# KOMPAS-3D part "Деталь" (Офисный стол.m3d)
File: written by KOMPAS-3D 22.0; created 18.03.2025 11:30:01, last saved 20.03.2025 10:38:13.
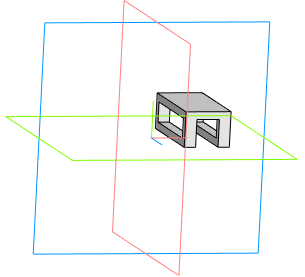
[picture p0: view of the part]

Document properties: Автор: Пользователь Windows; Полное имя файла: C:\Users\Student\Documents\Картошечка\База Сабнатика\Мебель\Офисный стол.m3d

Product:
- Part/product: Деталь
    Масса: 0.004864

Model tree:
1. Эскиз:1
2. Эскиз:2
3. Элемент по траектории:1
4. Элемент по траектории:2
5. Эскиз:3  (with: Элемент по траектории:2)
6. Элемент выдавливания:1  (with: Элемент по траектории:1)
     Расстояние 2 = -5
